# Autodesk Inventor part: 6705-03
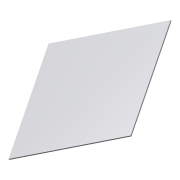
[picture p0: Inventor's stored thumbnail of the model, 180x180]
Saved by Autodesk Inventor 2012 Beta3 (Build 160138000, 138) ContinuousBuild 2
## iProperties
Created: 2011-02
Part Number: 6705-03
Material: Default
Document SubType Name: Modeling
Designer: Beta-8540w
Density: 1 g/cm^3
Author: Beta-8540w
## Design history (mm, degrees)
derived "c15-15.ipt" dims "d3" = 0, "drawer_depth" = 355.6, "bottom_width" = 349.25, "bottom_thickness" = 3.302
body "Solid1"
feature "Solid1::c15-15.ipt" dims "d3" = 0, "drawer_depth" = 355.6, "bottom_width" = 349.25, "bottom_thickness" = 3.302, "ScaleForDerivedMember" = 10
tag "TaggingFeature1"
